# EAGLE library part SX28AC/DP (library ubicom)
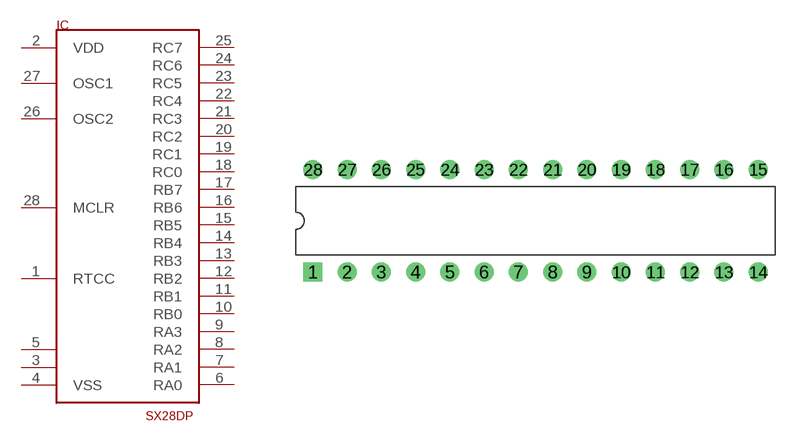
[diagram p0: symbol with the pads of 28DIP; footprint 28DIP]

Designator prefix IC

## SX28AC/DP  [28DIP]
1  RTCC  in
2  VDD  pwr
3  P$3  nc
4  VSS  pwr
5  P$5  nc
6  RA0
7  RA1
8  RA2
9  RA3
10  RB0
11  RB1
12  RB2
13  RB3
14  RB4
15  RB5
16  RB6
17  RB7
18  RC0
19  RC1
20  RC2
21  RC3
22  RC4
23  RC5
24  RC6
25  RC7
26  OSC2  out
27  OSC1  in
28  MCLR  in

## Footprint 28DIP (pad centres in mm)
drill 0.813 pad 1.397 square: 1 -10.16,-3.81
drill 0.813 pad 1.397 round: 2 -7.62,-3.81; 3 -5.08,-3.81; 4 -2.54,-3.81; 5 0,-3.81; 6 2.54,-3.81; 7 5.08,-3.81; 8 7.62,-3.81; 9 10.16,-3.81; 10 12.7,-3.81; 11 15.24,-3.81; 12 17.78,-3.81; 13 20.32,-3.81; 14 22.86,-3.81; 15 22.86,3.81; 16 20.32,3.81; 17 17.78,3.81; 18 15.24,3.81; 19 12.7,3.81; 20 10.16,3.81; 21 7.62,3.81; 22 5.08,3.81; 23 2.54,3.81; 24 0,3.81; 25 -2.54,3.81; 26 -5.08,3.81; 27 -7.62,3.81; 28 -10.16,3.81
